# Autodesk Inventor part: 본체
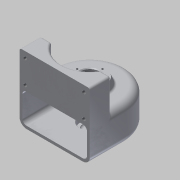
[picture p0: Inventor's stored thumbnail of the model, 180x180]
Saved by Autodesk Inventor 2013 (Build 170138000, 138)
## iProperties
Created: 2015-02
Part Number: 본체
Material: 알루미늄 6061
Document SubType Name: Modeling
Designer: Administrator
Density: 2.71 g/cm^3
Mass: 575.238 g
Surface Area: 710.538 cm^2
Volume: 212.265 cm^3
Author: Administrator
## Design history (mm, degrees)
sketch "스케치1"
  geometry: L1 (50, 0)-(50, -50); L2 (50, -50)-(-50, -50); L3 (-50, -50)-(-50, 0); A1 r 50 centre (0, 0) between (50, 0) and (-50, 0); 1 further point
  constraints: 6 end point, 2 point on circle, 2 tangent, 1 centre point, 1 coincident, 1 parallel, 1 perpendicular, 1 vertical
  dimensions: "d0" = 100 diameter of A1; "d1" = 50 distance of L1.start L1.end
extrude "돌출1" new body sketch "스케치1" stored distance "d2" = 50; taper "d3" = 0 deg
sketch "스케치2"
  geometry: L1 (0, 25)-(0, 35); L2 (50, 25)-(0, 25) reference; L3 (0, 35)-(21.36, 35); L4 (21.36, 35)-(25, 25); L5 (25, 25)-(0, 25); 1 further point
  constraints: 8 end point, 1 collinear, 1 midpoint, 1 parallel, 1 vertical, 1 vertical alignment
  dimensions: "d4" = 10 distance of L1.start L1.end; "d5" = 110 deg angle of L2 L4
revolve "회전1" sketch "스케치2" stored, may be unused: angle "d6" = 90 deg
sketch "스케치3"
  geometry: C1 r 20 at (0, 0); A1 r 50 centre (0, 0) between (50, 0) and (-50, 0) reference
  constraints: 1 centre point, 1 coincident
  dimensions: "d7" = 40 diameter of C1
extrude "돌출2" join sketch "스케치3" distance "d8" = 9; taper "d9" = 0 deg
sketch "스케치4"
  geometry: L1 (-50, 0)-(-50, -50) reference; L2 (-50, -50)-(50, -50) reference; L3 (50, -50)-(50, 0) reference; L4 (50, -50)-(50, -20); L5 (50, -20)-(34.641, -20); L6 (-50, -50)-(-50, -20); L7 (-50, -20)-(-34.641, -20); L8 (-50, -50)-(50, -50); A1 r 50 centre (0, 0) between (50, 0) and (-50, 0) reference; A2 r 40 centre (0, 0) between (-34.641, -20) and (34.641, -20)
  constraints: 10 end point, 2 perpendicular, 2 point on circle, 2 point on line, 1 centre point, 1 coincident, 1 parallel
  dimensions: "d10" = 80 diameter of A2; "d11" = 30 distance of L2.end L4.end; "d12" = 30 distance of L1.end L6.end
extrude "돌출3" join sketch "스케치4" distance "d13" = 45; taper "d14" = 0 deg
sketch "스케치5"
  geometry: L1 (0, 21)-(0, -21); L2 (0, 21)-(46, 21); L3 (46, 21)-(46, -21); L4 (46, -21)-(0, -21); L5 (50, -25)-(50, 25) reference; 2 further points
  constraints: 8 end point, 2 perpendicular, 1 coincident, 1 midpoint, 1 parallel, 1 vertical
  dimensions: "d15" = 42 distance of L1.start L1.end; "d16" = 4 distance between parallel lines of L5 L3
revolve "회전2" sketch "스케치5" stored, may be unused: angle "d17" = 90 deg
sketch "스케치6"
  geometry: L1 (100, 0)-(0, 0) reference; L2 (4, 46)-(96, 46); L3 (96, 46)-(96, 4); L4 (96, 4)-(4, 4); L5 (4, 4)-(4, 46); 3 further points
  constraints: 8 end point, 2 midpoint, 2 parallel, 1 horizontal, 1 perpendicular, 1 vertical alignment
  dimensions: "d18" = 4 distance between parallel lines of L4 L1; "d19" = 42 distance of L2.end L3.end; "d20" = 92 distance between parallel lines of L5 L3
extrude "돌출4" cut sketch "스케치6" distance "d21" = 50; taper "d22" = 0 deg
sketch "스케치7"
  geometry: L1 (-21.36, 35)-(21.36, 35) reference; L2 (-20, -34)-(20, -34) reference; L3 (46, -21)-(0, -21) reference; L4 (0, 35)-(0, -34); L5 (0, 35)-(14, 35); L6 (14, 35)-(14, 25); L7 (14, 25)-(10, 25); L8 (10, 25)-(10, -21); L9 (10, -21)-(14, -21); L10 (14, -21)-(14, -29); L11 (14, -29)-(10, -29); L12 (10, -29)-(10, -31); L13 (10, -31)-(0, -31); 1 further point
  constraints: 20 end point, 7 perpendicular, 4 point on line, 2 midpoint
  dimensions: "d23" = 28 diameter of L6 L4; "d25" = 20 diameter of L8 L4; "d26" = 10 distance between parallel lines of L1 L7; "d27" = 28 diameter of L10 L4; "d29" = 8 distance between parallel lines of L11 L3; "d30" = 2 distance of L11.end L12.end; "d31" = 20 diameter of L12 L4
revolve "회전3" sketch "스케치7" stored, may be unused: angle "d32" = 90 deg
sketch "스케치8"
  geometry: C1 r 14 at (0, 0) reference; 1 further point
  constraints: 1 vertical alignment
  dimensions: "d33" = 18 distance of C1.centre point (0, 18)
hole "구멍1" sketch "스케치8" at (0, 18) diameter "d34" = 2.459; stored, may be unused: countersink angle "d38" = 90 deg, drill point angle "d40" = 118 deg; dims "d35" = 6, "d36" = 4, "d37" = 2, "d39" = 9
sketch "스케치9"
  geometry: L1 (0, 95)-(100, 95) reference; L2 (0, 0)-(0, 95) reference; 5 further points
  constraints: 2 horizontal alignment, 2 vertical alignment
  dimensions: "d44" = 33 distance of point (8.25, 53) point (8.25, 86); "d46" = 83.5 distance of point (91.75, 86) point (8.25, 86); "d47" = 9 distance from line of L1 point (8.25, 86); "d48" = 8.25 distance from line of L2 point (8.25, 86)
hole "구멍2" sketch "스케치9" at (8.25, 86), (8.25, 53), (91.75, 53), (91.75, 86) diameter "d49" = 5.134; stored, may be unused: countersink angle "d53" = 90 deg, drill point angle "d55" = 118 deg; dims "d50" = 10, "d51" = 4, "d52" = 2, "d54" = 13
node "작업 평면1"
sketch "스케치10"
  geometry: L1 (-50, -25)-(50, -25) reference; 2 further points
  constraints: 1 coincident, 1 other
  dimensions: "d56" = 25 distance from line of point (0, 0) L1
feature "엠보싱1" sketch "스케치10" dims "d57" = 0.5, "d58" = 0
chamfer "모따기1" distance "d59" = 1; stored, may be unused: second distance "d60" = 2, angle "d61" = 45 deg
fillet "모깎기1" dims "d62" = 0.3
fillet "모깎기2" dims "d63" = 6
fillet "모깎기5" dims "d66" = 10
fillet "모깎기6" dims "d67" = 3
fillet "모깎기7" dims "d68" = 3
fillet "모깎기8" dims "d69" = 3
fillet "모깎기9" dims "d70" = 3
fillet "모깎기10" dims "d71" = 3
node "솔리드1"
pattern_circular "원형 패턴1" dims angle "d42" = 360 deg
